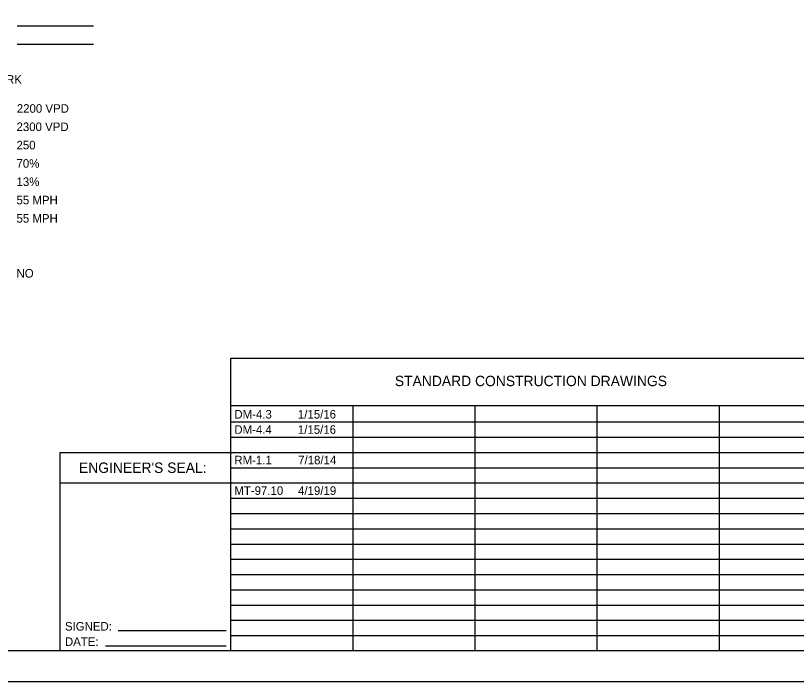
# Model space of a CAD drawing. Extents: x 0 to 84, y -106 to 22.
# Drawn here: x 7.72 to 20.51, y 0 to 10.9 of the extents above; entities that cross this region are included whole.
import ezdxf

# ---------------------------------------------------------------- set-up
doc = ezdxf.new("R2010")
doc.units = 0
for name, color, linetype in [('CS-ALGN-CNTR', 7, 'Continuous'), ('CS-ALGN-TEXT', 7, 'Continuous'), ('CS-ANNO', 7, 'Continuous'), ('CS-ANNO-MATC', 7, 'Continuous')]:
    doc.layers.add(name, color=color, linetype=linetype)

msp = doc.modelspace()

# ---------------------------------------------------------------- linework, layer by layer
at = {"layer": 'CS-ALGN-CNTR'}
msp.add_lwpolyline([(0, 0), (34, 0), (34, 22), (0, 22)], close=True, dxfattribs=at)
at = {"layer": 'CS-ALGN-TEXT'}
msp.add_lwpolyline([(1.5, 21.5), (33.5, 21.5), (33.5, 0.5), (1.5, 0.5)], close=True, dxfattribs=at)
at = {"layer": 'CS-ANNO'}
for p, q in [((9, 10.73), (7.75, 10.73)), ((9, 10.43), (7.75, 10.43)), ((11.25, 5.292), (24.7, 5.292)), ((11.25, 0.5), (11.25, 5.292)), ((11.25, 4.521), (24.7, 4.521)), ((13.25, 0.5), (13.25, 4.521)), ((15.25, 0.5), (15.25, 4.521)), ((17.25, 0.5), (17.25, 4.521)), ((19.25, 0.5), (19.25, 4.521)), ((11.25, 4.25), (24.7, 4.25)), ((11.25, 4), (24.7, 4)), ((8.45, 0.5), (8.45, 3.75)), ((8.45, 3.75), (11.25, 3.75)), ((11.25, 3.75), (24.7, 3.75)), ((11.25, 3.5), (24.7, 3.5)), ((8.45, 3.25), (11.25, 3.25)), ((11.25, 3.25), (24.7, 3.25)), ((11.25, 3), (24.7, 3)), ((11.25, 2.75), (24.7, 2.75)), ((11.25, 2.5), (24.7, 2.5)), ((11.25, 2.25), (24.7, 2.25)), ((11.25, 2), (24.7, 2)), ((11.25, 1.75), (24.7, 1.75)), ((11.25, 1.5), (24.7, 1.5)), ((11.25, 1.25), (24.7, 1.25)), ((11.25, 1), (24.7, 1)), ((11.25, 0.75), (24.7, 0.75))]:
    msp.add_line(p, q, dxfattribs=at)
at = {"layer": 'CS-ANNO-MATC'}
for p, q in [((9.401, 0.832), (11.171, 0.832)), ((9.193, 0.581), (11.171, 0.581))]:
    msp.add_line(p, q, dxfattribs=at)

# ---------------------------------------------------------------- texts
for s, height, p in [('NO ROADWAY WORK', 0.14, (5.89, 9.79)), ('2200 VPD', 0.14, (7.742, 9.314)), ('2300 VPD', 0.14, (7.737, 9.014)), ('250', 0.14, (7.737, 8.714)), ('70%', 0.14, (7.737, 8.414)), ('13%', 0.14, (7.737, 8.114)), ('55 MPH', 0.14, (7.737, 7.814)), ('55 MPH', 0.14, (7.737, 7.514)), ('NO', 0.14, (7.737, 6.614)), ('STANDARD CONSTRUCTION DRAWINGS', 0.17, (13.934, 4.836)), ('DM-4.3', 0.14, (11.305, 4.305)), ('1/15/16', 0.14, (12.346, 4.305)), ('DM-4.4', 0.14, (11.305, 4.055)), ('1/15/16', 0.14, (12.346, 4.055)), ("ENGINEER'S SEAL:", 0.17, (8.76, 3.415)), ('RM-1.1', 0.14, (11.305, 3.555)), ('7/18/14', 0.14, (12.351, 3.555)), ('4/19/19', 0.14, (12.349, 3.055)), ('MT-97.10', 0.14, (11.305, 3.055)), ('SIGNED:', 0.14, (8.53, 0.832)), ('DATE:', 0.14, (8.53, 0.581))]:
    msp.add_text(s, height=height, dxfattribs=at).set_placement(p)

doc.saveas('drawing.dxf')
